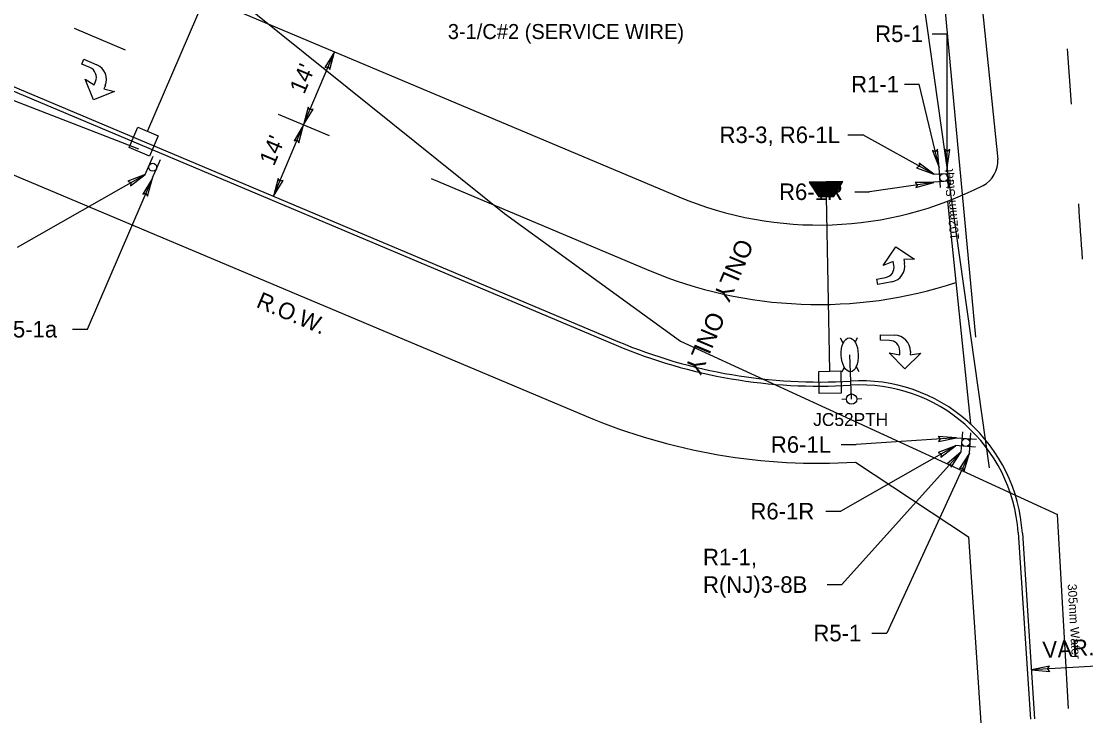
# Model space of a CAD drawing. Extents: x 488740 to 507913, y 466518 to 497949.
# Drawn here: x 503306.1 to 503498.8, y 495805.8 to 495932.7 of the extents above; entities that cross this region are included whole.
import ezdxf

# ---------------------------------------------------------------- set-up
doc = ezdxf.new("R2010")
doc.units = 0
for name, color, linetype in [('1', 7, 'Continuous'), ('11', 7, 'Continuous'), ('23', 7, 'Continuous'), ('36', 7, 'Continuous'), ('38', 7, 'Continuous'), ('41', 7, 'Continuous')]:
    doc.layers.add(name, color=color, linetype=linetype)

msp = doc.modelspace()

# ---------------------------------------------------------------- linework, layer by layer
at = {"layer": '1'}
for p, q in [((503471.88, 496014.92), (503482.9, 495907.73)), ((503126.85, 495994.96), (503413.81, 495874.09)), ((503127.14, 495995.66), (503414.1, 495874.78)), ((503121.44, 495982.11), (503408.4, 495861.23)), ((503268.83, 495966.81), (503425.13, 495900.97)), ((503457.09, 495874.6), (503457.49, 495875.48)), ((503454.91, 495874.46), (503454.43, 495875.35)), ((503456.43, 495864.35), (503456.11, 495872.35)), ((503455.11, 495870.12), (503454.67, 495869.22)), ((503457.26, 495870.21), (503457.74, 495869.34)), ((503455.53, 495864.31), (503454.66, 495864.27)), ((503457.4, 495864.38), (503458.3, 495864.42)), ((503457.13, 495852.93), (503477.59, 495839.42)), ((503477.59, 495839.42), (503479.82, 495805.75)), ((503486.61, 495840.19), (503488.84, 495806.41)), ((503487.37, 495840.06), (503489.59, 495806.46))]:
    msp.add_line(p, q, dxfattribs=at)
for points in [[(503325.59, 495909.86), (503327.15, 495913.55), (503330.83, 495912), (503329.28, 495908.31)], [(503450.56, 495865.36), (503450.48, 495869.36), (503454.48, 495869.44), (503454.56, 495865.44)]]:
    msp.add_lwpolyline(points, close=True, dxfattribs=at)
msp.add_circle((503456.44, 495864.33), 0.939, dxfattribs=at)
for centre, radius, start, end in [((503478.02, 495907.38), 4.9, 297.1014, 4.1335), ((503450.49, 495961.17), 65.32, 247.1579, 297.1014), ((503450.49, 495961.17), 94.49, 247.1579, 273.51), ((503450.49, 495961.17), 93.74, 247.1579, 273.51), ((503458.03, 495838.26), 29.39, 3.51, 93.51), ((503458.03, 495838.26), 28.64, 3.8622, 93.51), ((503450.49, 495961.16), 108.43, 247.1579, 273.51)]:
    msp.add_arc(centre, radius, start, end, dxfattribs=at)
msp.add_ellipse((503456.11, 495872.35), major_axis=(0.12, -3.07), ratio=0.504, dxfattribs=at)
at = {"layer": '23'}
for p, q in [((503478.95, 495875.52), (503464.57, 496029.78)), ((503481.44, 495851.92), (503458.62, 496013.71)), ((503280.37, 495988.85), (503393.56, 495897.96)), ((503133.33, 495985.05), (503327.28, 495909.62)), ((503328.98, 495912.96), (503344.08, 495947.95)), ((503448.82, 495903.56), (503454.81, 495903.68)), ((503448.87, 495903.49), (503454.77, 495903.61)), ((503448.91, 495903.43), (503454.73, 495903.55)), ((503448.95, 495903.36), (503454.69, 495903.48)), ((503449, 495903.29), (503454.65, 495903.41)), ((503449.04, 495903.23), (503454.61, 495903.34)), ((503449.09, 495903.16), (503454.57, 495903.27)), ((503449.13, 495903.09), (503454.53, 495903.2)), ((503449.17, 495903.03), (503454.49, 495903.14)), ((503449.22, 495902.96), (503454.45, 495903.07)), ((503449.26, 495902.89), (503454.41, 495903)), ((503449.3, 495902.83), (503454.37, 495902.93)), ((503449.35, 495902.76), (503454.33, 495902.86)), ((503449.39, 495902.69), (503454.28, 495902.79)), ((503449.43, 495902.63), (503454.24, 495902.72)), ((503449.48, 495902.56), (503454.2, 495902.66)), ((503449.52, 495902.49), (503454.16, 495902.59)), ((503449.56, 495902.43), (503454.12, 495902.52)), ((503449.61, 495902.36), (503454.08, 495902.45)), ((503449.65, 495902.29), (503454.04, 495902.38)), ((503449.7, 495902.23), (503454, 495902.31)), ((503449.74, 495902.16), (503453.96, 495902.25)), ((503449.78, 495902.09), (503453.92, 495902.18)), ((503449.83, 495902.03), (503453.88, 495902.11)), ((503449.87, 495901.96), (503453.84, 495902.04)), ((503449.91, 495901.89), (503453.79, 495901.97)), ((503449.96, 495901.83), (503453.75, 495901.9)), ((503450, 495901.76), (503453.71, 495901.84)), ((503450.04, 495901.69), (503453.67, 495901.77)), ((503450.09, 495901.63), (503453.63, 495901.7)), ((503450.13, 495901.56), (503453.59, 495901.63)), ((503450.17, 495901.49), (503453.55, 495901.56)), ((503450.22, 495901.43), (503453.51, 495901.49)), ((503450.26, 495901.36), (503453.47, 495901.43)), ((503450.31, 495901.29), (503453.43, 495901.36)), ((503450.35, 495901.23), (503453.39, 495901.29)), ((503450.39, 495901.16), (503453.35, 495901.22)), ((503450.44, 495901.09), (503453.31, 495901.15)), ((503450.48, 495901.03), (503453.26, 495901.08)), ((503452.52, 495869.4), (503451.87, 495900.99)), ((503451.87, 495900.99), (503451.87, 495900.99)), ((503393.56, 495897.96), (503425.43, 495874.84)), ((503425.43, 495874.84), (503493.76, 495843.43)), ((503495.75, 495808.31), (503493.76, 495843.43))]:
    msp.add_line(p, q, dxfattribs=at)
msp.add_lwpolyline([(503450.52, 495900.96), (503453.22, 495901.02), (503454.86, 495903.75), (503448.78, 495903.63)], close=True, dxfattribs=at)
at = {"layer": '36'}
for p, q in [((503315.65, 495931.46), (503324.89, 495927.58)), ((503496.28, 495917.73), (503495.56, 495927.72)), ((503317.01, 495924.97), (503317.39, 495925.86)), ((503317.39, 495925.86), (503319.75, 495924.86)), ((503318.49, 495924.35), (503317.01, 495924.97)), ((503319.16, 495918.5), (503317.62, 495922.28)), ((503317.62, 495922.28), (503319.27, 495921.24)), ((503319.27, 495921.24), (503319.52, 495921.83)), ((503322.94, 495920.04), (503319.16, 495918.5)), ((503321.29, 495921.08), (503321.04, 495920.49)), ((503321.04, 495920.49), (503322.94, 495920.04)), ((503352.58, 495915.91), (503361.81, 495912.03)), ((503380.27, 495904.25), (503419.65, 495887.66)), ((503473.83, 495900.16), (503477.98, 495859.85)), ((503462.17, 495888.54), (503464.45, 495891.92)), ((503464.45, 495891.92), (503467.83, 495889.64)), ((503464, 495889.22), (503462.17, 495888.54)), ((503464.12, 495888.59), (503464, 495889.22)), ((503467.83, 495889.64), (503465.88, 495889.58)), ((503465.88, 495889.58), (503466.01, 495888.95)), ((503461.03, 495886.03), (503462.6, 495886.33)), ((503461.21, 495885.08), (503461.03, 495886.03)), ((503463.73, 495885.57), (503461.21, 495885.08)), ((503461.67, 495874.99), (503461.69, 495875.95)), ((503461.69, 495875.95), (503464.25, 495875.91)), ((503463.28, 495874.96), (503461.67, 495874.99)), ((503466.08, 495869.79), (503463.24, 495872.72)), ((503463.24, 495872.72), (503465.16, 495872.37)), ((503465.16, 495872.37), (503465.17, 495873.01)), ((503469.01, 495872.63), (503466.08, 495869.79)), ((503467.09, 495872.98), (503467.08, 495872.34)), ((503467.08, 495872.34), (503469.01, 495872.63))]:
    msp.add_line(p, q, dxfattribs=at)
for centre, radius, start, end in [((503317.74, 495922.58), 1.92, 337.157, 67.157), ((503318.63, 495922.2), 2.88, 337.157, 67.157), ((496341.87, 495401.78), 7173, 3.900289, 3.980294), ((503463.18, 495888.4), 2.88, 280.9995, 10.9995), ((503450.49, 495961.17), 79.71, 247.2422, 288.1704), ((503462.23, 495888.22), 1.92, 280.9995, 10.9995), ((503464.21, 495873.02), 2.88, 359.0902, 89.0902), ((503463.25, 495873.04), 1.92, 359.0902, 89.0902)]:
    msp.add_arc(centre, radius, start, end, dxfattribs=at)
at = {"layer": '38'}
for p, q in [((503357.19, 495913.97), (503362.78, 495927.23)), ((503351.75, 495901.05), (503357.19, 495913.97)), ((503502.89, 495816.12), (503489, 495815.31))]:
    msp.add_line(p, q, dxfattribs=at)
for points in [[(503362.78, 495927.23), (503361.06, 495924.37), (503361.63, 495924.51), (503361.93, 495924)], [(503357.19, 495913.97), (503358.91, 495916.83), (503358.34, 495916.69), (503358.04, 495917.2)], [(503357.19, 495913.97), (503355.47, 495911.11), (503356.05, 495911.25), (503356.35, 495910.74)], [(503351.75, 495901.05), (503353.47, 495903.91), (503352.9, 495903.77), (503352.6, 495904.28)], [(503489, 495815.31), (503492.33, 495815.03), (503491.95, 495815.48), (503492.28, 495815.97)]]:
    msp.add_lwpolyline(points, close=True, dxfattribs=at)
at = {"layer": '41'}
for p, q in [((503471.06, 495930.47), (503473.77, 495930.47)), ((503473.78, 495906.21), (503473.77, 495930.47)), ((503466, 495921.34), (503468.71, 495921.34)), ((503472.29, 495906.24), (503468.71, 495921.34)), ((503455.76, 495912.18), (503458.47, 495912.18)), ((503471.33, 495905.04), (503458.47, 495912.18)), ((503328.5, 495904.99), (503329.97, 495908.34)), ((503331.22, 495907.66), (503329.75, 495904.31)), ((503472.53, 495902.63), (503472.33, 495906.28)), ((503305.38, 495891.86), (503328.5, 495904.99)), ((503471.33, 495905.04), (503474.99, 495905.25)), ((503473.75, 495906.24), (503473.96, 495902.59)), ((503318.06, 495876.99), (503329.82, 495904.31)), ((503471.31, 495903.56), (503459.71, 495901.87)), ((503474.95, 495903.83), (503471.29, 495903.62)), ((503457, 495901.87), (503459.71, 495901.87)), ((503315.35, 495876.99), (503318.06, 495876.99)), ((503476.31, 495854.76), (503476.57, 495858.42)), ((503477.97, 495858.2), (503477.72, 495854.55)), ((503475.46, 495857.33), (503457.25, 495856.12)), ((503475.42, 495857.31), (503479.08, 495857.06)), ((503475.25, 495855.87), (503454.5, 495844.05)), ((503454.54, 495856.12), (503457.25, 495856.12)), ((503476.31, 495854.76), (503454.7, 495830.75)), ((503477.78, 495854.55), (503462.8, 495821.98)), ((503478.86, 495855.65), (503475.21, 495855.91)), ((503451.79, 495844.05), (503454.5, 495844.05)), ((503451.99, 495830.75), (503454.7, 495830.75)), ((503460.09, 495821.98), (503462.8, 495821.98))]:
    msp.add_line(p, q, dxfattribs=at)
for points in [[(503472.29, 495906.24), (503471.99, 495909.56), (503471.61, 495909.11), (503471.07, 495909.34)], [(503473.78, 495906.21), (503474.25, 495909.52), (503473.78, 495909.16), (503473.3, 495909.52)], [(503471.33, 495905.04), (503468.67, 495907.06), (503468.75, 495906.48), (503468.21, 495906.23)], [(503328.5, 495904.99), (503325.39, 495903.76), (503325.93, 495903.53), (503325.86, 495902.94)], [(503329.82, 495904.31), (503328.08, 495901.46), (503328.65, 495901.6), (503328.95, 495901.09)], [(503471.31, 495903.56), (503467.97, 495903.55), (503468.39, 495903.14), (503468.1, 495902.62)], [(503475.46, 495857.33), (503472.13, 495857.58), (503472.51, 495857.14), (503472.19, 495856.64)], [(503475.25, 495855.87), (503472.14, 495854.64), (503472.69, 495854.41), (503472.61, 495853.82)], [(503476.31, 495854.76), (503473.75, 495852.62), (503474.34, 495852.57), (503474.45, 495851.99)], [(503477.78, 495854.55), (503475.97, 495851.75), (503476.55, 495851.87), (503476.83, 495851.35)]]:
    msp.add_lwpolyline(points, close=True, dxfattribs=at)
for centre in [(503329.86, 495906.32), (503329.86, 495906.32), (503473.14, 495904.44), (503473.14, 495904.44), (503473.14, 495904.44), (503473.14, 495904.44), (503477.14, 495856.48), (503477.14, 495856.48), (503477.14, 495856.48), (503477.14, 495856.48)]:
    msp.add_circle(centre, 0.721, dxfattribs=at)

# ---------------------------------------------------------------- texts
at = {"layer": '1'}
msp.add_text('R.O.W.', height=2.993, rotation=337.1579, dxfattribs=at).set_placement((503348.44, 495881.07))
msp.add_text('JC52PTH', height=2.344, dxfattribs=at).set_placement((503449.49, 495859.47))
at = {"layer": '11'}
msp.add_text('3-1/C#2 (SERVICE WIRE)                         ', height=2.7163, dxfattribs=at).set_placement((503383.31, 495929.52))
at = {"layer": '23'}
for s, height, rotation, p in [('102mm Steet', 1.6205, 95.1971, (503475.93, 495893.23)), ('305mm Water', 1.6204, 273.2441, (503495.57, 495830.84))]:
    msp.add_text(s, height=height, rotation=rotation, dxfattribs=at).set_placement(p)
at = {"layer": '36'}
for p in [(503435.84, 495893.62), (503430.68, 495880.43)]:
    msp.add_text('ONLY', height=3.193, rotation=247.1557, dxfattribs=at).set_placement(p)
at = {"layer": '38'}
for s, rotation, p in [("14'", 67.1563, (503357.3, 495919.39)), ("14'", 67.1561, (503351.83, 495906.4)), ('VAR.', 3.3115, (503491.13, 495817.43))]:
    msp.add_text(s, height=2.993, rotation=rotation, dxfattribs=at).set_placement(p)
at = {"layer": '41'}
for s, height, p in [('R5-1', 2.993, (503460.71, 495928.98)), ('R1-1', 2.993, (503456.35, 495919.85)), ('R3-3, R6-1L', 2.9928, (503432.53, 495910.69)), ('R6-1R', 2.993, (503443.3, 495900.38)), ('R5-1a', 2.993, (503301.66, 495875.49)), ('R6-1L', 2.993, (503441.82, 495854.62)), ('R6-1R', 2.993, (503438.12, 495842.55)), ('R1-1,', 2.993, (503429.53, 495834.25)), ('R(NJ)3-8B', 2.993, (503429.53, 495829.26)), ('R5-1', 2.993, (503449.52, 495820.49))]:
    msp.add_text(s, height=height, dxfattribs=at).set_placement(p)

doc.saveas('drawing.dxf')
